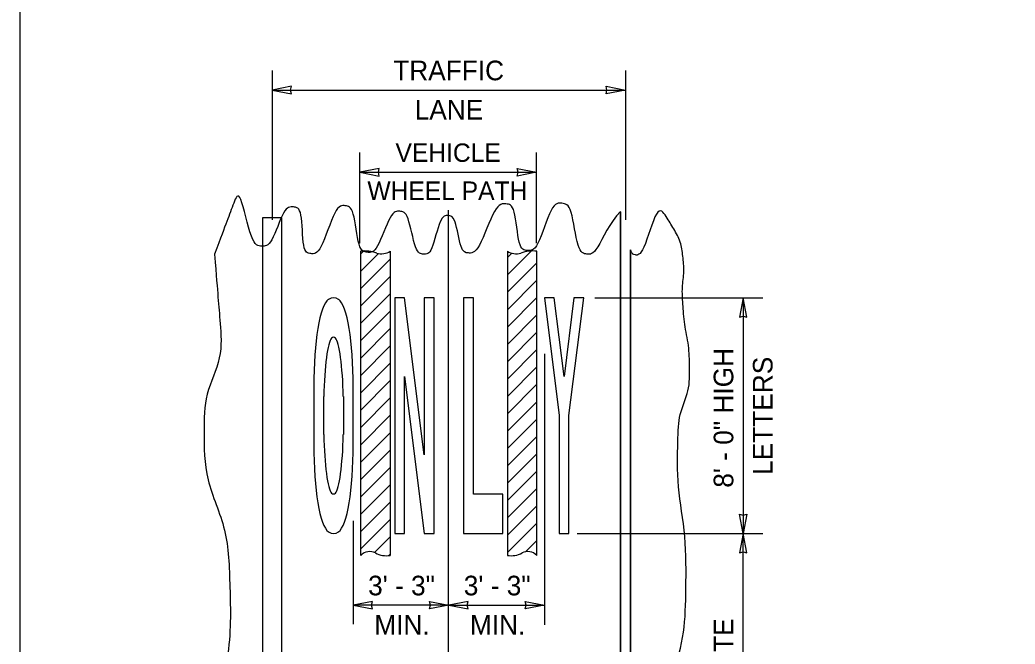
# Model space of a CAD drawing. Extents: x 99862 to 103151, y 100000 to 105076.
# Drawn here: x 99862 to 100673, y 103529 to 104038 of the extents above; entities that cross this region are included whole.
import ezdxf

# ---------------------------------------------------------------- set-up
doc = ezdxf.new("R2010")
doc.units = 0
for name, color, linetype in [('Level 1', 7, 'Continuous'), ('Level 15', 7, 'Continuous'), ('Level 2', 7, 'Continuous'), ('Level 20', 7, 'Continuous'), ('Level 3', 7, 'Continuous'), ('Level 6', 7, 'Continuous'), ('Level 8', 7, 'Continuous')]:
    doc.layers.add(name, color=color, linetype=linetype)

msp = doc.modelspace()

# ---------------------------------------------------------------- linework, layer by layer
at = {"layer": 'Level 1'}
msp.add_lwpolyline([(99862, 102999.5), (103151, 102999.5), (103151, 105075.5), (99862, 105075.5)], close=True, dxfattribs=at)
at = {"layer": 'Level 15'}
for p, q in [((100067.7, 103996.3), (100067.7, 103874.6)), ((100355.7, 103996.3), (100355.7, 103874.6)), ((100067.7, 103980.3), (100355.7, 103980.3)), ((100139.26, 103855.54), (100139.26, 103929.3)), ((100283.29, 103855.54), (100283.29, 103929.3)), ((100139.29, 103913.3), (100283.29, 103913.3)), ((100211.29, 103882.36), (100211.29, 103514.84)), ((100330.7, 103810.94), (100467.7, 103810.94)), ((100451.7, 103810.93), (100451.7, 103618.93)), ((100289.72, 103765.23), (100289.72, 103544.44)), ((100133.72, 103629.06), (100133.72, 103544.84)), ((100316.49, 103618.94), (100467.7, 103618.94)), ((100451.7, 103373.93), (100451.7, 103618.93)), ((100211.69, 103560.44), (100133.72, 103560.44)), ((100211.69, 103560.44), (100289.69, 103560.44))]:
    msp.add_line(p, q, dxfattribs=at)
for points in [[(100067.7, 103980.3), (100083.42, 103977.22), (100082.7, 103980.3), (100083.42, 103983.39)], [(100355.7, 103980.3), (100339.97, 103977.22), (100340.7, 103980.3), (100339.97, 103983.39)], [(100139.29, 103913.3), (100155.02, 103910.22), (100154.29, 103913.3), (100155.02, 103916.39)], [(100283.29, 103913.3), (100267.57, 103910.22), (100268.3, 103913.3), (100267.57, 103916.39)], [(100451.7, 103810.93), (100448.61, 103795.21), (100451.7, 103795.93), (100454.78, 103795.21)], [(100451.7, 103618.93), (100448.61, 103634.66), (100451.7, 103633.93), (100454.78, 103634.66)], [(100451.7, 103618.93), (100448.61, 103603.21), (100451.7, 103603.93), (100454.78, 103603.21)], [(100133.72, 103560.44), (100149.44, 103557.36), (100148.71, 103560.44), (100149.44, 103563.53)], [(100211.69, 103560.44), (100195.97, 103557.36), (100196.69, 103560.44), (100195.97, 103563.53)], [(100211.69, 103560.44), (100227.42, 103557.36), (100226.69, 103560.44), (100227.42, 103563.53)], [(100289.69, 103560.44), (100273.97, 103557.36), (100274.69, 103560.44), (100273.97, 103563.53)]]:
    msp.add_lwpolyline(points, close=True, dxfattribs=at)
at = {"layer": 'Level 2'}
for p, q in [((100075.7, 103876.27), (100059.7, 103876.27)), ((100059.7, 103876.27), (100059.7, 103064.85)), ((100075.7, 103064.85), (100075.7, 103876.27))]:
    msp.add_line(p, q, dxfattribs=at)
for points in [[(100075.7, 103876.27), (100059.7, 103876.27), (100059.7, 103058.78)], [(100075.7, 103058.78), (100075.7, 103876.27)]]:
    msp.add_lwpolyline(points, dxfattribs=at)
at = {"layer": 'Level 3'}
for points in [[(100351.7, 103073.28), (100351.7, 103881.23)], [(100359.92, 103850.06), (100359.92, 103072.81)]]:
    msp.add_lwpolyline(points, dxfattribs=at)
for points in [[(100351.7, 103881.23), (100342.98, 103872.38), (100331.45, 103845.66), (100324.48, 103846.58), (100316.55, 103847.63), (100312.08, 103887.03), (100304.02, 103887.99), (100295.68, 103888.99), (100283.82, 103848.7), (100275.58, 103849.58), (100268.43, 103850.34), (100265.87, 103886.77), (100258.62, 103887.49), (100249.76, 103888.37), (100235.72, 103846.86), (100227.19, 103847.58), (100221.42, 103848.06), (100217.17, 103877.64), (100211.23, 103878.01), (100204.79, 103878.42), (100197.71, 103846.17), (100191.27, 103846.58), (100184.36, 103847.02), (100178.67, 103881.01), (100171.82, 103881.5), (100164.51, 103882.04), (100152.95, 103847.42), (100145.38, 103848.08), (100137.92, 103848.73), (100134.4, 103885.12), (100127.42, 103885.99), (100119.39, 103887), (100107.04, 103846.04), (100098.98, 103847.08), (100092.22, 103847.95), (100092.48, 103884.35), (100085.01, 103885), (100077.4, 103885.66), (100066.99, 103852.82), (100059.07, 103853.07), (100051.01, 103853.32), (100041.29, 103901.29), (100036.37, 103888.24), (100031.13, 103874.35), (100025.89, 103860.47), (100020.65, 103846.58)], [(100359.92, 103072.81), (100366.05, 103080.91), (100372.52, 103092.25), (100378.07, 103092.25), (100385.79, 103092.25), (100393.31, 103051.59), (100396.52, 103064.83), (100403.33, 103084.8), (100401.64, 103113.15), (100400.27, 103141.14), (100398.83, 103170.24), (100392.28, 103199.38), (100391.54, 103228.44), (100390.26, 103278.09), (100410.9, 103327.63), (100410.49, 103377.11), (100410.24, 103408.19), (100394.28, 103438.79), (100394.53, 103469.9), (100394.8, 103504.04), (100404.51, 103538.36), (100405.01, 103572.67), (100405.58, 103617.17), (100397.53, 103656.98), (100398.52, 103696.41), (100399.01, 103716.02), (100408.35, 103735.22), (100408, 103754.78), (100407.69, 103772.03), (100403.6, 103789.36), (100402.51, 103806.66), (100401.71, 103819.4), (100403.97, 103832.28), (100402.51, 103845.08), (100401.2, 103856.62), (100395.22, 103867.22), (100389.04, 103877.01), (100381.84, 103888.4), (100369.98, 103844.95), (100363.1, 103846.07), (100361.83, 103846.28), (100360.81, 103847.79), (100359.92, 103850.06)], [(100020.65, 103846.58), (100022.15, 103828.29), (100023.65, 103810), (100025.14, 103791.7), (100027.58, 103761.89), (100012.19, 103732.45), (100012.17, 103702.9), (100012.15, 103662.56), (100031.89, 103622.51), (100033.13, 103577.17), (100034.96, 103517.26), (100012.54, 103456.11), (100015.17, 103396.08), (100016.11, 103374.45), (100027.71, 103353.43), (100027.64, 103331.72), (100027.52, 103295.4), (100017.05, 103258.99), (100017.91, 103222.47), (100018.56, 103194.86), (100020.47, 103167.26), (100021.15, 103139.65), (100021.53, 103124.53), (100020.93, 103109.38), (100021.15, 103094.25), (100021.36, 103088.27), (100024.8, 103074.64), (100030.38, 103061.34), (100039.01, 103040.81), (100070.76, 103115.25), (100079.34, 103095.78), (100082.65, 103088.26), (100084.03, 103087.78), (100087.31, 103080.08), (100089.16, 103075.71), (100091.01, 103071.36), (100093.49, 103067.33), (100102.49, 103052.74), (100119.28, 103097.75), (100129.16, 103096.25), (100136.79, 103095.08), (100138.95, 103069.71), (100147.87, 103069.33), (100158.79, 103068.86), (100170.28, 103096.04), (100182.04, 103095.75), (100193.13, 103095.48), (100204.92, 103072.88), (100215.72, 103072.82), (100225.12, 103072.76), (100233.48, 103095.06), (100241.41, 103095.25), (100249.05, 103095.44), (100255.79, 103072.23), (100263.36, 103071.82), (100271.53, 103071.38), (100280.86, 103096.72), (100289.05, 103096.25), (100296.79, 103095.8), (100301.87, 103071.47), (100309.26, 103070.82), (100317.52, 103070.1), (100329.68, 103096.48), (100337.95, 103095.75), (100343.57, 103095.25), (100347.17, 103080.8), (100351.7, 103073.28)]]:
    msp.add_open_spline(points, degree=3, dxfattribs=at)
at = {"layer": 'Level 6'}
for p, q in [((100139.95, 103846.76), (100142.28, 103849.09)), ((100139.95, 103832.62), (100154.45, 103847.13)), ((100259.45, 103829.59), (100278.92, 103849.06)), ((100259.45, 103843.74), (100263.14, 103847.43)), ((100359.7, 103849.94), (100359.7, 103073.3)), ((100139.95, 103818.48), (100163.95, 103842.48)), ((100259.45, 103815.45), (100283.45, 103839.45)), ((100139.95, 103804.33), (100163.95, 103828.33)), ((100259.45, 103801.31), (100283.45, 103825.31)), ((100139.95, 103790.19), (100163.95, 103814.19)), ((100259.45, 103787.17), (100283.45, 103811.17)), ((100139.95, 103776.05), (100163.95, 103800.05)), ((100259.45, 103773.02), (100283.45, 103797.02)), ((100139.95, 103761.91), (100163.95, 103785.91)), ((100259.45, 103758.88), (100283.45, 103782.88)), ((100139.95, 103747.76), (100163.95, 103771.76)), ((100259.45, 103744.74), (100283.45, 103768.74)), ((100139.95, 103733.62), (100163.95, 103757.62)), ((100259.45, 103730.6), (100283.45, 103754.6)), ((100139.95, 103719.48), (100163.95, 103743.48)), ((100259.45, 103716.46), (100283.45, 103740.46)), ((100139.95, 103705.34), (100163.95, 103729.34)), ((100259.45, 103702.31), (100283.45, 103726.31)), ((100139.95, 103691.2), (100163.95, 103715.2)), ((100259.45, 103688.17), (100283.45, 103712.17)), ((100139.95, 103677.05), (100163.95, 103701.05)), ((100259.45, 103674.03), (100283.45, 103698.03)), ((100139.95, 103662.91), (100163.95, 103686.91)), ((100259.45, 103659.89), (100283.45, 103683.89)), ((100139.95, 103648.77), (100163.95, 103672.77)), ((100259.45, 103645.75), (100283.45, 103669.75)), ((100139.95, 103634.63), (100163.95, 103658.63)), ((100259.45, 103631.6), (100283.45, 103655.6)), ((100139.95, 103620.49), (100163.95, 103644.49)), ((100259.45, 103617.46), (100283.45, 103641.46)), ((100139.95, 103606.34), (100163.95, 103630.34)), ((100259.45, 103603.32), (100283.45, 103627.32)), ((100151.09, 103603.35), (100163.95, 103616.2)), ((100274.22, 103603.95), (100283.45, 103613.18)), ((100162.78, 103600.89), (100163.95, 103602.06))]:
    msp.add_line(p, q, dxfattribs=at)
for points in [[(100351.7, 103881.19), (100351.7, 103073.3)], [(100075.7, 103098.97), (100075.7, 103875.09)], [(100059.7, 103852.82), (100059.7, 103084.2)], [(100139.95, 103600.99), (100139.95, 103848.99)], [(100163.95, 103848.99), (100163.95, 103600.99)], [(100259.45, 103848.99), (100259.45, 103600.99)], [(100283.45, 103600.99), (100283.45, 103848.99)]]:
    msp.add_lwpolyline(points, dxfattribs=at)
for centre, radius, start, end in [((100142.95, 103817.91), 31.23, 71.3233, 95.51281), ((100156.85, 103859.94), 13.05, 252.58763, 302.9427), ((100266.54, 103859.94), 13.05, 237.0573, 287.41237), ((100280.45, 103817.91), 31.23, 84.48719, 108.6767), ((100147.26, 103594.13), 10.02, 62.1057, 136.81894), ((100160.95, 103619.99), 19.24, 242.10273, 278.97263), ((100262.45, 103619.99), 19.24, 261.02737, 297.89727), ((100276.14, 103594.13), 10.02, 43.18106, 117.8943)]:
    msp.add_arc(centre, radius, start, end, dxfattribs=at)
at = {"layer": 'Level 8'}
for p, q in [((100175.72, 103810.94), (100167.72, 103810.94)), ((100167.72, 103810.94), (100167.72, 103618.94)), ((100191.72, 103682.94), (100175.72, 103810.94)), ((100199.72, 103810.94), (100191.72, 103810.94)), ((100191.72, 103810.94), (100191.72, 103682.94)), ((100199.72, 103618.94), (100199.72, 103810.94)), ((100231.72, 103810.94), (100223.72, 103810.94)), ((100223.72, 103810.94), (100223.72, 103618.94)), ((100231.72, 103650.94), (100231.72, 103810.94)), ((100297.72, 103810.94), (100289.72, 103810.94)), ((100289.72, 103810.94), (100301.72, 103714.94)), ((100305.72, 103746.94), (100297.72, 103810.94)), ((100313.72, 103810.94), (100305.72, 103746.94)), ((100309.72, 103714.94), (100321.72, 103810.94)), ((100321.72, 103810.94), (100313.72, 103810.94)), ((100175.72, 103746.94), (100191.72, 103618.94)), ((100175.72, 103618.94), (100175.72, 103746.94)), ((100101.72, 103738.44), (100101.72, 103714.94)), ((100109.72, 103714.94), (100109.72, 103730.44)), ((100125.72, 103730.44), (100125.72, 103714.94)), ((100101.72, 103714.94), (100101.72, 103691.44)), ((100109.72, 103699.44), (100109.72, 103714.94)), ((100125.72, 103714.94), (100125.72, 103699.44)), ((100301.72, 103714.94), (100301.72, 103618.94)), ((100309.72, 103618.94), (100309.72, 103714.94)), ((100255.72, 103650.94), (100231.72, 103650.94)), ((100255.72, 103618.94), (100255.72, 103650.94)), ((100167.72, 103618.94), (100175.72, 103618.94)), ((100191.72, 103618.94), (100199.72, 103618.94)), ((100223.72, 103618.94), (100230.72, 103618.94)), ((100230.72, 103618.94), (100231.72, 103618.94)), ((100231.72, 103618.94), (100255.72, 103618.94)), ((100301.72, 103618.94), (100309.72, 103618.94))]:
    msp.add_line(p, q, dxfattribs=at)
for points in [[(100175.72, 103618.94), (100175.72, 103746.94), (100191.72, 103618.94), (100199.72, 103618.94), (100199.72, 103810.94), (100191.72, 103810.94), (100191.72, 103682.94), (100175.72, 103810.94), (100167.72, 103810.94), (100167.72, 103618.94), (100175.72, 103618.94)], [(100167.72, 103810.94), (100167.72, 103618.94), (100175.72, 103618.94), (100175.72, 103746.94), (100191.72, 103618.94), (100199.72, 103618.94), (100199.72, 103810.94), (100191.72, 103810.94), (100191.72, 103682.94), (100175.72, 103810.94), (100167.72, 103810.94)], [(100255.72, 103650.94), (100231.72, 103650.94), (100231.72, 103810.94), (100223.72, 103810.94), (100223.72, 103618.94), (100230.72, 103618.94), (100231.72, 103618.94), (100255.72, 103618.94), (100255.72, 103650.94)], [(100255.72, 103650.94), (100231.72, 103650.94), (100231.72, 103810.94), (100223.72, 103810.94), (100223.72, 103618.94), (100230.72, 103618.94), (100231.72, 103618.94), (100255.72, 103618.94), (100255.72, 103650.94)], [(100309.72, 103618.94), (100309.72, 103714.94), (100321.72, 103810.94), (100313.72, 103810.94), (100305.72, 103746.94), (100297.72, 103810.94), (100289.72, 103810.94), (100301.72, 103714.94), (100301.72, 103618.94), (100309.72, 103618.94)], [(100309.72, 103618.94), (100309.72, 103714.94), (100321.72, 103810.94), (100313.72, 103810.94), (100305.72, 103746.94), (100297.72, 103810.94), (100289.72, 103810.94), (100301.72, 103714.94), (100301.72, 103618.94), (100309.72, 103618.94)], [(100101.72, 103738.44), (100101.72, 103714.94), (100101.72, 103691.44)], [(100101.72, 103738.44), (100101.72, 103714.94), (100101.72, 103691.44)], [(100133.71, 103691.44), (100133.71, 103714.94), (100133.71, 103738.44)], [(100133.71, 103691.44), (100133.71, 103714.94), (100133.71, 103738.44)], [(100109.72, 103699.44), (100109.72, 103714.94), (100109.72, 103730.44)], [(100109.72, 103699.44), (100109.72, 103714.94), (100109.72, 103730.44)], [(100125.72, 103730.44), (100125.72, 103714.94), (100125.72, 103699.44)], [(100125.72, 103730.44), (100125.72, 103714.94), (100125.72, 103699.44)]]:
    msp.add_lwpolyline(points, dxfattribs=at)
for centre, major_axis, ratio, start_param, end_param in [((100113.71, 103642.63), (-4.19, -168.31), 0.199299, 3.026472, 3.266466), ((100113.71, 103642.63), (-4.19, -168.31), 0.199299, 3.026472, 3.266466), ((100117.71, 103730.78), (2, -79.67), 0.199299, 3.270146, 4.611011), ((100117.71, 103730.78), (2, -79.67), 0.199299, 3.270146, 4.611011), ((100117.72, 103730.82), (-1.98, -79.63), 0.199299, 1.671694, 3.012648), ((100117.72, 103730.82), (-1.98, -79.63), 0.199299, 1.671694, 3.012648), ((100115.59, 103730.31), (-1.13, -48.13), 0.12203, 3.268534, 4.712481), ((100115.59, 103730.31), (-1.13, -48.13), 0.12203, 3.268534, 4.712481), ((100114.53, 103639.96), (-3.25, -138.86), 0.12203, 3.042542, 3.248083), ((100114.53, 103639.96), (-3.25, -138.86), 0.12203, 3.042542, 3.248083), ((100119.84, 103730.31), (1.13, -48.13), 0.12203, 1.570704, 3.018848), ((100119.84, 103730.31), (1.13, -48.13), 0.12203, 1.570704, 3.018848), ((100115.59, 103699.58), (1.13, -48.13), 0.12203, 4.712297, 6.156244), ((100115.59, 103699.58), (1.13, -48.13), 0.12203, 4.712297, 6.156244), ((100119.84, 103699.58), (-1.13, -48.13), 0.12203, 0.122745, 1.570889), ((100119.84, 103699.58), (-1.13, -48.13), 0.12203, 0.122745, 1.570889), ((100117.71, 103699.11), (-2, -79.67), 0.199299, 4.813767, 6.154632), ((100117.71, 103699.11), (-2, -79.67), 0.199299, 4.813767, 6.154632), ((100117.72, 103699.07), (1.98, -79.63), 0.199299, 0.128945, 1.469898), ((100117.72, 103699.07), (1.98, -79.63), 0.199299, 0.128945, 1.469898), ((100114.53, 103789.93), (3.25, -138.86), 0.12203, 6.176695, 6.382236), ((100114.53, 103789.93), (3.25, -138.86), 0.12203, 6.176695, 6.382236), ((100113.71, 103787.25), (4.19, -168.31), 0.199299, 6.158312, 6.398306), ((100113.71, 103787.25), (4.19, -168.31), 0.199299, 6.158312, 6.398306)]:
    msp.add_ellipse(centre, major_axis=major_axis, ratio=ratio, start_param=start_param, end_param=end_param, dxfattribs=at)

# ---------------------------------------------------------------- texts
at = {"layer": 'Level 20'}
for s, height, rotation, p in [('TRAFFIC', 16, 360, (100166.43, 103988.3)), ('LANE', 16, 360, (100183.92, 103956.3)), ('VEHICLE', 15, 360, (100168.27, 103921.8)), ('WHEEL PATH', 15, 360, (100145.35, 103890.8)), ('8\' - 0" HIGH', 16, 90, (100443.7, 103656.18)), ('LETTERS', 16, 90, (100475.7, 103666.63)), ('3\' - 3"', 16, 360, (100145.93, 103568.44)), ('3\' - 3"', 16, 360, (100223.93, 103568.44)), ('MIN.', 16, 360, (100150.99, 103536.44)), ('MIN.', 16, 360, (100228.99, 103536.44)), ('SEE NOTE', 16, 90, (100443.7, 103441.49))]:
    msp.add_text(s, height=height, rotation=rotation, dxfattribs=at).set_placement(p)

doc.saveas('drawing.dxf')
